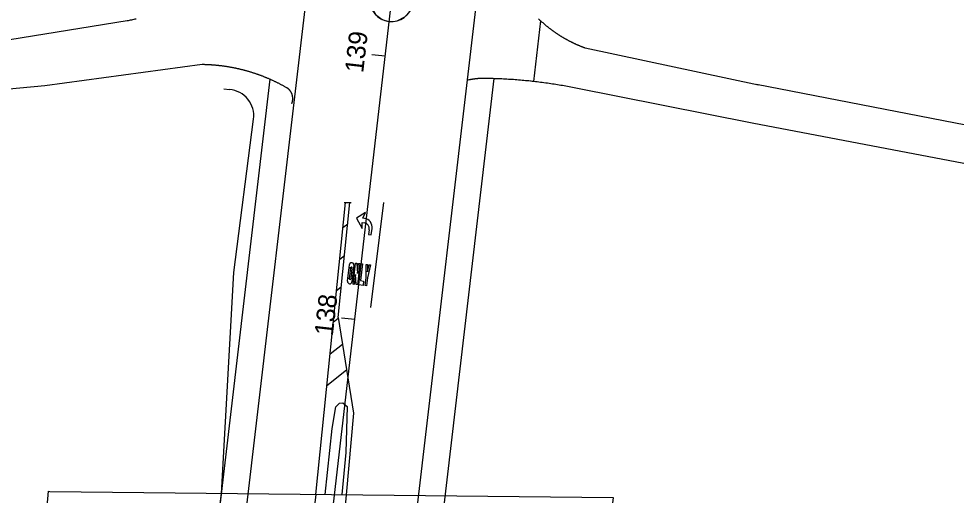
# Model space of a CAD drawing. Extents: x 2318076 to 2324211, y 613525 to 629939.
# Drawn here: x 2320472.4 to 2320826.1, y 628302.7 to 628482.6 of the extents above; entities that cross this region are included whole.
import ezdxf

# ---------------------------------------------------------------- set-up
doc = ezdxf.new("R2010")
doc.units = 0
for name, color, linetype in [('BR_X_Slab_Object', 7, 'Continuous'), ('GE_P_CL_50', 7, 'Continuous'), ('PM_P_Cells', 7, 'Continuous'), ('PM_P_Channelizing_Line', 7, 'Continuous'), ('PM_P_CL_Double_Solid', 7, 'Continuous'), ('PM_P_Island', 7, 'Continuous'), ('PM_P_Transverse_Line', 7, 'Continuous'), ('PM_X_CL_Double_Solid', 7, 'Continuous'), ('PV_P_EOP', 7, 'Continuous'), ('PV_P_Shoulder', 7, 'Continuous'), ('RD_X_Concrete_Barrier', 7, 'Continuous'), ('RD_X_GR_Lt', 7, 'Continuous'), ('RS_Raster1', 7, 'Continuous')]:
    doc.layers.add(name, color=color, linetype=linetype)

msp = doc.modelspace()

# ---------------------------------------------------------------- linework, layer by layer
at = {"layer": 'BR_X_Slab_Object'}
msp.add_lwpolyline([(2320484.11, 628304.16), (2320696.64, 628301.84), (2320691.49, 628259.41), (2320480.05, 628262.45), (2320483.63, 628304.22), (2320484.11, 628304.16)], dxfattribs=at)
at = {"layer": 'GE_P_CL_50'}
for p, q in [((2320610.64, 628468.38), (2320605.67, 628468.95)), ((2320599.16, 628369.04), (2320594.19, 628369.61))]:
    msp.add_line(p, q, dxfattribs=at)
msp.add_lwpolyline([(2320485.22, 627375.57), (2320502.11, 627520.92), (2320519.22, 627676.47), (2320531.82, 627783.89), (2320546.8, 627927.12), (2320554.45, 627991.34), (2320572.51, 628138.41), (2320649.52, 628804.84), (2320678.77, 629064.5), (2320690.76, 629163.78), (2320713.75, 629362.45), (2320725.26, 629461.78), (2320736.97, 629561.09), (2320748.4, 629660.43), (2320759.09, 629759.86), (2320769.62, 629859.3), (2320777.51, 629931.12), (2320778.25, 629937.84)], dxfattribs=at)
at = {"layer": 'PM_P_Cells'}
for p, q in [((2320603.22, 628409.38), (2320599.87, 628407.29)), ((2320602.23, 628407.26), (2320603.22, 628409.38)), ((2320603.22, 628409.38), (2320603.22, 628409.38)), ((2320599.87, 628407.29), (2320601.99, 628403.41)), ((2320602.89, 628407.16), (2320602.23, 628407.26)), ((2320601.99, 628403.41), (2320601.99, 628405.68)), ((2320601.99, 628405.68), (2320602.69, 628405.57)), ((2320604.62, 628402.96), (2320604.35, 628401.12)), ((2320605.34, 628400.97), (2320605.7, 628403.43)), ((2320602.04, 628401.46), (2320602.04, 628401.46)), ((2320604.35, 628401.12), (2320605.34, 628400.97)), ((2320596.6, 628384.63), (2320597.08, 628388.6)), ((2320597.08, 628388.6), (2320597.21, 628389.76)), ((2320597.57, 628388.55), (2320597.08, 628388.6)), ((2320597.08, 628388.6), (2320597.57, 628388.55)), ((2320597.57, 628388.55), (2320597.1, 628384.57)), ((2320597.76, 628384.49), (2320598.23, 628388.47)), ((2320598.87, 628389.57), (2320598.12, 628383.28)), ((2320598.52, 628382.39), (2320599.46, 628390.33)), ((2320599.46, 628390.33), (2320599.96, 628390.27)), ((2320599.96, 628390.27), (2320600.18, 628386.47)), ((2320601.12, 628390.14), (2320600.17, 628382.19)), ((2320600.18, 628386.47), (2320600.62, 628390.2)), ((2320600.62, 628390.2), (2320601.12, 628390.14)), ((2320600.67, 628382.13), (2320601.62, 628390.08)), ((2320601.2, 628390.13), (2320601.2, 628390.13)), ((2320602.11, 628390.02), (2320601.36, 628383.73)), ((2320601.62, 628390.08), (2320602.11, 628390.02)), ((2320603.42, 628384.83), (2320603.44, 628389.86)), ((2320603.44, 628389.86), (2320603.93, 628389.8)), ((2320605.09, 628389.66), (2320603.92, 628384.77)), ((2320603.93, 628389.8), (2320603.95, 628387.11)), ((2320603.95, 628387.11), (2320604.59, 628389.72)), ((2320604.59, 628389.72), (2320605.09, 628389.66)), ((2320596.46, 628383.47), (2320596.6, 628384.63)), ((2320596.6, 628384.63), (2320597.1, 628384.57)), ((2320597.1, 628384.57), (2320596.6, 628384.63)), ((2320599.46, 628386.05), (2320599.01, 628382.33)), ((2320599.68, 628382.25), (2320599.46, 628386.05)), ((2320603.07, 628381.85), (2320603.42, 628384.83)), ((2320603.92, 628384.77), (2320603.56, 628381.79)), ((2320599.01, 628382.33), (2320598.52, 628382.39)), ((2320600.17, 628382.19), (2320599.68, 628382.25)), ((2320600.25, 628382.18), (2320600.25, 628382.18)), ((2320602.32, 628381.94), (2320600.67, 628382.13)), ((2320601.36, 628383.73), (2320602.52, 628383.59)), ((2320602.52, 628383.59), (2320602.32, 628381.94)), ((2320603.56, 628381.79), (2320603.07, 628381.85))]:
    msp.add_line(p, q, dxfattribs=at)
for centre, radius, start, end in [((2320602.46, 628403.91), 3.28, 351.5547, 82.4632), ((2320602.35, 628403.3), 2.3, 351.5547, 81.5547), ((2320598.04, 628389.66), 0.833, 353.2057, 173.2057), ((2320597.9, 628388.51), 0.333, 353.2057, 173.2057), ((2320597.29, 628383.38), 0.833, 173.2057, 353.2057), ((2320597.43, 628384.53), 0.333, 173.2057, 353.2057)]:
    msp.add_arc(centre, radius, start, end, dxfattribs=at)
at = {"layer": 'PM_P_Channelizing_Line'}
msp.add_lwpolyline([(2320605.23, 628373.54), (2320610.1, 628413.2)], dxfattribs=at)
at = {"layer": 'PM_P_CL_Double_Solid'}
for p, q in [((2320584.51, 628303.06), (2320595.7, 628413.25)), ((2320592.91, 628369.76), (2320597.33, 628413.25)), ((2320592.91, 628369.76), (2320598.66, 628333.76)), ((2320598.66, 628333.76), (2320595.94, 628302.94))]:
    msp.add_line(p, q, dxfattribs=at)
at = {"layer": 'PM_P_Island'}
msp.add_lwpolyline([(2320622.04, 628497.59), (2320606, 628499.42), (2320604.93, 628490.08), (2320605.45, 628486.7), (2320606.99, 628484.17), (2320609.45, 628482.31), (2320611.9, 628481.55), (2320612.52, 628481.49), (2320613.49, 628481.49), (2320615.17, 628481.76), (2320618.12, 628483.27), (2320620.03, 628485.47), (2320620.95, 628487.79)], close=True, dxfattribs=at)
at = {"layer": 'PM_P_Transverse_Line'}
for p, q in [((2320596.5, 628405.08), (2320594.73, 628403.68)), ((2320595.29, 628393.15), (2320593.52, 628391.75)), ((2320594.07, 628381.22), (2320592.31, 628379.82)), ((2320592.97, 628369.38), (2320591.09, 628367.89)), ((2320594.53, 628359.64), (2320589.88, 628355.96)), ((2320596.08, 628349.9), (2320588.67, 628344.03))]:
    msp.add_line(p, q, dxfattribs=at)
at = {"layer": 'PM_X_CL_Double_Solid'}
msp.add_line((2320595.15, 628413.25), (2320597.78, 628413.25), dxfattribs=at)
at = {"layer": 'PV_P_EOP'}
for p, q in [((2320590.74, 628574.92), (2320513.05, 627912.02)), ((2320576.7, 627905.37), (2320654.32, 628567.57)), ((2320666.71, 628458.87), (2320669.35, 628481.73)), ((2320584.51, 628303.06), (2320566.09, 628143.74)), ((2320595.94, 628302.94), (2320581.17, 628143.24))]:
    msp.add_line(p, q, dxfattribs=at)
for points in [[(2320668.46, 628482.56), (2320668.59, 628482.43), (2320668.72, 628482.31), (2320668.85, 628482.19), (2320668.99, 628482.06), (2320669.35, 628481.73)], [(2320649.48, 628460), (2320649.4, 628460), (2320649.31, 628460.01), (2320649.23, 628460.01), (2320649.15, 628460.02), (2320649.07, 628460.02), (2320648.98, 628460.02), (2320648.9, 628460.03), (2320648.82, 628460.03), (2320648.74, 628460.03), (2320648.65, 628460.04), (2320648.57, 628460.04), (2320648.49, 628460.04), (2320648.4, 628460.04), (2320648.32, 628460.04), (2320648.24, 628460.04), (2320648.15, 628460.05), (2320648.07, 628460.05), (2320647.99, 628460.05), (2320647.91, 628460.05), (2320647.82, 628460.05), (2320647.74, 628460.05), (2320647.66, 628460.05), (2320647.57, 628460.04), (2320647.49, 628460.04), (2320647.41, 628460.04), (2320647.32, 628460.04), (2320647.24, 628460.04), (2320647.16, 628460.04), (2320647.08, 628460.03), (2320646.99, 628460.03), (2320646.91, 628460.03), (2320646.83, 628460.03), (2320646.74, 628460.02), (2320646.66, 628460.02), (2320646.58, 628460.01), (2320646.49, 628460.01), (2320646.41, 628460.01), (2320646.33, 628460), (2320646.25, 628460), (2320646.16, 628459.99), (2320646.08, 628459.99), (2320646, 628459.98), (2320645.91, 628459.97), (2320645.83, 628459.97), (2320645.75, 628459.96), (2320645.66, 628459.95), (2320645.58, 628459.95), (2320645.5, 628459.94), (2320645.42, 628459.93), (2320645.33, 628459.93), (2320645.25, 628459.92), (2320645.17, 628459.91), (2320645.09, 628459.9), (2320645, 628459.89), (2320644.92, 628459.88), (2320644.84, 628459.87), (2320644.75, 628459.86), (2320644.67, 628459.85), (2320644.59, 628459.84), (2320644.51, 628459.83), (2320644.42, 628459.82), (2320644.34, 628459.81), (2320644.26, 628459.8), (2320644.18, 628459.79), (2320644.1, 628459.78), (2320644.01, 628459.77), (2320643.93, 628459.76), (2320643.85, 628459.74), (2320643.77, 628459.73), (2320643.68, 628459.72), (2320643.6, 628459.71), (2320643.52, 628459.69), (2320643.44, 628459.68), (2320643.36, 628459.66), (2320643.27, 628459.65), (2320643.19, 628459.64), (2320643.11, 628459.62), (2320643.03, 628459.61), (2320642.95, 628459.59), (2320642.87, 628459.58), (2320642.78, 628459.56), (2320642.7, 628459.55), (2320642.62, 628459.53), (2320642.54, 628459.51), (2320642.46, 628459.5), (2320642.38, 628459.48), (2320642.3, 628459.46), (2320642.22, 628459.45), (2320641.63, 628459.32)], [(2320666.71, 628458.87), (2320664.83, 628459.07), (2320664.19, 628459.13), (2320663.56, 628459.19), (2320662.92, 628459.25), (2320662.28, 628459.31), (2320661.64, 628459.37), (2320661, 628459.42), (2320660.36, 628459.47), (2320659.72, 628459.52), (2320659.08, 628459.57), (2320658.44, 628459.61), (2320657.81, 628459.65), (2320657.17, 628459.69), (2320656.53, 628459.73), (2320655.89, 628459.77), (2320655.25, 628459.8), (2320654.61, 628459.83), (2320653.96, 628459.86), (2320653.32, 628459.89), (2320652.68, 628459.91), (2320652.04, 628459.93), (2320651.4, 628459.95), (2320650.76, 628459.97), (2320650.12, 628459.99), (2320649.48, 628460)]]:
    msp.add_lwpolyline(points, dxfattribs=at)
msp.add_arc((2320613.03, 628489.59), 8.12, 175.7115, 350.2041, dxfattribs=at)
at = {"layer": 'PV_P_Shoulder'}
for p, q in [((2320567.18, 628459.79), (2320515.22, 628016.39)), ((2320599.22, 628011.62), (2320651.77, 628459.98))]:
    msp.add_line(p, q, dxfattribs=at)
at = {"layer": 'RD_X_Concrete_Barrier'}
msp.add_line((2320532.74, 628165.9), (2320548.86, 628303.45), dxfattribs=at)
msp.add_lwpolyline([(2320588, 628303.03), (2320590.67, 628327.94), (2320592.06, 628336.09), (2320593.44, 628337.44), (2320594.67, 628337.67), (2320596.35, 628336.22), (2320595.82, 628318.82), (2320594.3, 628302.96)], dxfattribs=at)
at = {"layer": 'RD_X_GR_Lt'}
for p, q in [((2320549.79, 628456.05), (2320551.93, 628455.87)), ((2320553.6, 628386.82), (2320561.02, 628444.63)), ((2320548.86, 628303.45), (2320553.6, 628386.82))]:
    msp.add_line(p, q, dxfattribs=at)
msp.add_arc((2320551.1, 628445.9), 10, 352.6854, 85.2335, dxfattribs=at)
at = {"layer": 'RS_Raster1'}
for p, q in [((2320429.11, 628468.24), (2320513.35, 628481.85)), ((2320686.14, 628471.54), (2320751.52, 628457.58)), ((2320749.08, 628443.19), (2320681.94, 628456.49)), ((2320872.26, 628434.14), (2320750.75, 628457.74)), ((2320902.18, 628413.99), (2320749.08, 628443.19))]:
    msp.add_line(p, q, dxfattribs=at)
for points in [[(2320513.35, 628481.85), (2320513.78, 628481.94), (2320514.2, 628482.03), (2320514.63, 628482.12), (2320515.05, 628482.21), (2320515.48, 628482.3), (2320515.9, 628482.39), (2320516.33, 628482.49), (2320516.75, 628482.58)], [(2320668.46, 628482.56), (2320668.59, 628482.43), (2320668.72, 628482.31), (2320668.85, 628482.19), (2320668.99, 628482.06), (2320669.12, 628481.94), (2320669.25, 628481.82), (2320669.38, 628481.69), (2320669.52, 628481.57), (2320669.65, 628481.45), (2320669.79, 628481.33), (2320669.92, 628481.21), (2320670.06, 628481.09), (2320670.19, 628480.97), (2320670.33, 628480.85), (2320670.47, 628480.73), (2320670.6, 628480.62), (2320670.74, 628480.5), (2320670.88, 628480.38), (2320671.02, 628480.27), (2320671.16, 628480.15), (2320671.3, 628480.04), (2320671.44, 628479.92), (2320671.58, 628479.81), (2320671.72, 628479.69), (2320671.86, 628479.58), (2320672, 628479.47), (2320672.14, 628479.35), (2320672.28, 628479.24), (2320672.42, 628479.13), (2320672.57, 628479.02), (2320672.71, 628478.91), (2320672.85, 628478.8), (2320673, 628478.69), (2320673.14, 628478.58), (2320673.29, 628478.47), (2320673.43, 628478.37), (2320673.58, 628478.26), (2320673.73, 628478.15), (2320673.87, 628478.05), (2320674.02, 628477.94), (2320674.17, 628477.83), (2320674.31, 628477.73), (2320674.46, 628477.63), (2320674.61, 628477.52), (2320674.76, 628477.42), (2320674.91, 628477.32), (2320675.06, 628477.21), (2320675.21, 628477.11), (2320675.36, 628477.01), (2320675.51, 628476.91), (2320675.66, 628476.81), (2320675.81, 628476.71), (2320675.96, 628476.61), (2320676.11, 628476.52), (2320676.27, 628476.42), (2320676.42, 628476.32), (2320676.57, 628476.23), (2320676.72, 628476.13), (2320676.88, 628476.03), (2320677.03, 628475.94), (2320677.19, 628475.84), (2320677.34, 628475.75), (2320677.5, 628475.66), (2320677.65, 628475.57), (2320677.81, 628475.47), (2320677.96, 628475.38), (2320678.12, 628475.29), (2320678.28, 628475.2), (2320678.43, 628475.11), (2320678.59, 628475.02), (2320678.75, 628474.93), (2320678.91, 628474.84), (2320679.07, 628474.76), (2320679.22, 628474.67), (2320679.38, 628474.58), (2320679.54, 628474.5), (2320679.7, 628474.41), (2320679.86, 628474.33), (2320680.02, 628474.24), (2320680.18, 628474.16), (2320680.34, 628474.08), (2320680.5, 628473.99), (2320680.66, 628473.91), (2320680.83, 628473.83), (2320680.99, 628473.75), (2320681.15, 628473.67), (2320681.31, 628473.59), (2320681.48, 628473.51), (2320681.64, 628473.43), (2320681.8, 628473.35), (2320681.97, 628473.28), (2320682.13, 628473.2), (2320682.29, 628473.12), (2320682.46, 628473.05), (2320682.62, 628472.97), (2320682.79, 628472.9), (2320682.95, 628472.83), (2320683.12, 628472.75), (2320683.28, 628472.68), (2320683.45, 628472.61), (2320683.62, 628472.54), (2320683.78, 628472.47), (2320683.95, 628472.4), (2320684.12, 628472.33), (2320684.28, 628472.26), (2320684.45, 628472.19), (2320684.62, 628472.12), (2320684.79, 628472.06), (2320684.96, 628471.99), (2320685.12, 628471.92), (2320685.29, 628471.86), (2320685.46, 628471.79), (2320685.63, 628471.73), (2320685.8, 628471.67), (2320685.97, 628471.6), (2320686.14, 628471.54)], [(2320541.61, 628465.25), (2320482.26, 628457.22), (2320418.88, 628451.31), (2320347.06, 628441.39), (2320257.15, 628427.56), (2320159.66, 628413.29), (2320059.39, 628398.63), (2319964.41, 628383.7), (2319830.88, 628363.16), (2319830.71, 628363.13), (2319830.71, 628363.13)], [(2320573.86, 628456.31), (2320573.66, 628456.43), (2320573.46, 628456.54), (2320573.26, 628456.66), (2320573.06, 628456.77), (2320572.85, 628456.88), (2320572.65, 628457), (2320572.45, 628457.11), (2320572.25, 628457.22), (2320572.04, 628457.33), (2320571.84, 628457.44), (2320571.63, 628457.55), (2320571.43, 628457.66), (2320571.22, 628457.77), (2320571.02, 628457.87), (2320570.81, 628457.98), (2320570.61, 628458.09), (2320570.4, 628458.19), (2320570.19, 628458.3), (2320569.98, 628458.4), (2320569.78, 628458.5), (2320569.57, 628458.6), (2320569.36, 628458.71), (2320569.15, 628458.81), (2320568.94, 628458.91), (2320568.73, 628459), (2320568.52, 628459.1), (2320568.31, 628459.2), (2320568.1, 628459.3), (2320567.89, 628459.39), (2320567.68, 628459.49), (2320567.47, 628459.58), (2320567.26, 628459.68), (2320567.04, 628459.77), (2320566.83, 628459.86), (2320566.62, 628459.95), (2320566.41, 628460.05), (2320566.19, 628460.14), (2320565.98, 628460.22), (2320565.76, 628460.31), (2320565.55, 628460.4), (2320565.33, 628460.49), (2320565.12, 628460.57), (2320564.9, 628460.66), (2320564.69, 628460.74), (2320564.47, 628460.83), (2320564.26, 628460.91), (2320564.04, 628460.99), (2320563.82, 628461.08), (2320563.61, 628461.16), (2320563.39, 628461.24), (2320563.17, 628461.32), (2320562.95, 628461.4), (2320562.73, 628461.47), (2320562.51, 628461.55), (2320562.3, 628461.63), (2320562.08, 628461.7), (2320561.86, 628461.78), (2320561.64, 628461.85), (2320561.42, 628461.92), (2320561.2, 628462), (2320560.98, 628462.07), (2320560.76, 628462.14), (2320560.54, 628462.21), (2320560.31, 628462.28), (2320560.09, 628462.35), (2320559.87, 628462.42), (2320559.65, 628462.48), (2320559.43, 628462.55), (2320559.21, 628462.61), (2320558.98, 628462.68), (2320558.76, 628462.74), (2320558.54, 628462.81), (2320558.31, 628462.87), (2320558.09, 628462.93), (2320557.87, 628462.99), (2320557.64, 628463.05), (2320557.42, 628463.11), (2320557.19, 628463.17), (2320556.97, 628463.23), (2320556.75, 628463.28), (2320556.52, 628463.34), (2320556.3, 628463.39), (2320556.07, 628463.45), (2320555.84, 628463.5), (2320555.62, 628463.55), (2320555.39, 628463.61), (2320555.17, 628463.66), (2320554.94, 628463.71), (2320554.71, 628463.76), (2320554.49, 628463.81), (2320554.26, 628463.85), (2320554.03, 628463.9), (2320553.81, 628463.95), (2320553.58, 628463.99), (2320553.35, 628464.04), (2320553.12, 628464.08), (2320552.9, 628464.13), (2320552.67, 628464.17), (2320552.44, 628464.21), (2320552.21, 628464.25), (2320551.98, 628464.29), (2320551.76, 628464.33), (2320551.53, 628464.37), (2320551.3, 628464.41), (2320551.07, 628464.44), (2320550.84, 628464.48), (2320550.61, 628464.51), (2320550.38, 628464.55), (2320550.15, 628464.58), (2320549.92, 628464.61), (2320549.69, 628464.65), (2320549.46, 628464.68), (2320549.23, 628464.71), (2320549.01, 628464.74), (2320548.78, 628464.77), (2320548.54, 628464.79), (2320548.31, 628464.82), (2320548.08, 628464.85), (2320547.85, 628464.87), (2320547.62, 628464.9), (2320547.39, 628464.92), (2320547.16, 628464.94), (2320546.93, 628464.97), (2320546.7, 628464.99), (2320546.47, 628465.01), (2320546.24, 628465.03), (2320546.01, 628465.05), (2320545.78, 628465.06), (2320545.55, 628465.08), (2320545.31, 628465.1), (2320545.08, 628465.11), (2320544.85, 628465.13), (2320544.62, 628465.14), (2320544.39, 628465.16), (2320544.16, 628465.17), (2320543.93, 628465.18), (2320543.7, 628465.19), (2320543.46, 628465.2), (2320543.23, 628465.21), (2320543, 628465.22), (2320542.77, 628465.22), (2320542.54, 628465.23), (2320542.31, 628465.24), (2320542.07, 628465.24), (2320541.84, 628465.25), (2320541.61, 628465.25)], [(2320649.48, 628460), (2320649.4, 628460), (2320649.31, 628460.01), (2320649.23, 628460.01), (2320649.15, 628460.02), (2320649.07, 628460.02), (2320648.98, 628460.02), (2320648.9, 628460.03), (2320648.82, 628460.03), (2320648.74, 628460.03), (2320648.65, 628460.04), (2320648.57, 628460.04), (2320648.49, 628460.04), (2320648.4, 628460.04), (2320648.32, 628460.04), (2320648.24, 628460.04), (2320648.15, 628460.05), (2320648.07, 628460.05), (2320647.99, 628460.05), (2320647.91, 628460.05), (2320647.82, 628460.05), (2320647.74, 628460.05), (2320647.66, 628460.05), (2320647.57, 628460.04), (2320647.49, 628460.04), (2320647.41, 628460.04), (2320647.32, 628460.04), (2320647.24, 628460.04), (2320647.16, 628460.04), (2320647.08, 628460.03), (2320646.99, 628460.03), (2320646.91, 628460.03), (2320646.83, 628460.03), (2320646.74, 628460.02), (2320646.66, 628460.02), (2320646.58, 628460.01), (2320646.49, 628460.01), (2320646.41, 628460.01), (2320646.33, 628460), (2320646.25, 628460), (2320646.16, 628459.99), (2320646.08, 628459.99), (2320646, 628459.98), (2320645.91, 628459.97), (2320645.83, 628459.97), (2320645.75, 628459.96), (2320645.66, 628459.95), (2320645.58, 628459.95), (2320645.5, 628459.94), (2320645.42, 628459.93), (2320645.33, 628459.93), (2320645.25, 628459.92), (2320645.17, 628459.91), (2320645.09, 628459.9), (2320645, 628459.89), (2320644.92, 628459.88), (2320644.84, 628459.87), (2320644.75, 628459.86), (2320644.67, 628459.85), (2320644.59, 628459.84), (2320644.51, 628459.83), (2320644.42, 628459.82), (2320644.34, 628459.81), (2320644.26, 628459.8), (2320644.18, 628459.79), (2320644.1, 628459.78), (2320644.01, 628459.77), (2320643.93, 628459.76), (2320643.85, 628459.74), (2320643.77, 628459.73), (2320643.68, 628459.72), (2320643.6, 628459.71), (2320643.52, 628459.69), (2320643.44, 628459.68), (2320643.36, 628459.66), (2320643.27, 628459.65), (2320643.19, 628459.64), (2320643.11, 628459.62), (2320643.03, 628459.61), (2320642.95, 628459.59), (2320642.87, 628459.58), (2320642.78, 628459.56), (2320642.7, 628459.55), (2320642.62, 628459.53), (2320642.54, 628459.51), (2320642.46, 628459.5), (2320642.38, 628459.48), (2320642.3, 628459.46), (2320642.22, 628459.45), (2320641.81, 628459.36)], [(2320681.94, 628456.49), (2320681.31, 628456.61), (2320680.68, 628456.74), (2320680.05, 628456.86), (2320679.42, 628456.97), (2320678.79, 628457.09), (2320678.16, 628457.2), (2320677.53, 628457.31), (2320676.9, 628457.42), (2320676.27, 628457.53), (2320675.63, 628457.63), (2320675, 628457.73), (2320674.37, 628457.83), (2320673.73, 628457.93), (2320673.1, 628458.03), (2320672.46, 628458.12), (2320671.83, 628458.21), (2320671.2, 628458.3), (2320670.56, 628458.39), (2320669.92, 628458.47), (2320669.29, 628458.55), (2320668.65, 628458.63), (2320668.02, 628458.71), (2320667.38, 628458.79), (2320666.74, 628458.86), (2320666.11, 628458.93), (2320665.47, 628459), (2320664.83, 628459.07), (2320664.19, 628459.13), (2320663.56, 628459.19), (2320662.92, 628459.25), (2320662.28, 628459.31), (2320661.64, 628459.37), (2320661, 628459.42), (2320660.36, 628459.47), (2320659.72, 628459.52), (2320659.08, 628459.57), (2320658.44, 628459.61), (2320657.81, 628459.65), (2320657.17, 628459.69), (2320656.53, 628459.73), (2320655.89, 628459.77), (2320655.25, 628459.8), (2320654.61, 628459.83), (2320653.96, 628459.86), (2320653.32, 628459.89), (2320652.68, 628459.91), (2320652.04, 628459.93), (2320651.4, 628459.95), (2320650.76, 628459.97), (2320650.12, 628459.99), (2320649.48, 628460)], [(2320575.44, 628450.58), (2320575.47, 628450.66), (2320575.5, 628450.74), (2320575.53, 628450.82), (2320575.56, 628450.9), (2320575.58, 628450.98), (2320575.61, 628451.06), (2320575.63, 628451.14), (2320575.65, 628451.22), (2320575.67, 628451.3), (2320575.69, 628451.38), (2320575.71, 628451.46), (2320575.72, 628451.55), (2320575.74, 628451.63), (2320575.75, 628451.71), (2320575.76, 628451.8), (2320575.77, 628451.88), (2320575.78, 628451.96), (2320575.79, 628452.05), (2320575.79, 628452.13), (2320575.8, 628452.22), (2320575.8, 628452.3), (2320575.8, 628452.38), (2320575.8, 628452.47), (2320575.8, 628452.55), (2320575.79, 628452.64), (2320575.79, 628452.72), (2320575.78, 628452.8), (2320575.78, 628452.89), (2320575.77, 628452.97), (2320575.76, 628453.05), (2320575.75, 628453.14), (2320575.73, 628453.22), (2320575.72, 628453.3), (2320575.7, 628453.39), (2320575.69, 628453.47), (2320575.67, 628453.55), (2320575.65, 628453.63), (2320575.62, 628453.71), (2320575.6, 628453.79), (2320575.58, 628453.87), (2320575.55, 628453.96), (2320575.52, 628454.03), (2320575.5, 628454.11), (2320575.47, 628454.19), (2320575.43, 628454.27), (2320575.4, 628454.35), (2320575.37, 628454.42), (2320575.33, 628454.5), (2320575.3, 628454.58), (2320575.26, 628454.65), (2320575.22, 628454.73), (2320575.18, 628454.8), (2320575.14, 628454.87), (2320575.09, 628454.95), (2320575.05, 628455.02), (2320575, 628455.09), (2320574.96, 628455.16), (2320574.91, 628455.23), (2320574.86, 628455.3), (2320574.81, 628455.36), (2320574.76, 628455.43), (2320574.71, 628455.49), (2320574.65, 628455.56), (2320574.6, 628455.62), (2320574.54, 628455.69), (2320574.48, 628455.75), (2320574.43, 628455.81), (2320574.37, 628455.87), (2320574.31, 628455.93), (2320574.25, 628455.99), (2320574.18, 628456.04), (2320574.12, 628456.1), (2320574.06, 628456.15), (2320573.99, 628456.21), (2320573.93, 628456.26), (2320573.86, 628456.31)]]:
    msp.add_lwpolyline(points, dxfattribs=at)

# ---------------------------------------------------------------- texts
at = {"layer": 'GE_P_CL_50'}
for s, p in [('139', (2320602.34, 628461.91)), ('138', (2320590.88, 628362.68))]:
    msp.add_text(s, height=7, rotation=83.4084, dxfattribs=at).set_placement(p)

doc.saveas('drawing.dxf')
